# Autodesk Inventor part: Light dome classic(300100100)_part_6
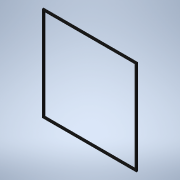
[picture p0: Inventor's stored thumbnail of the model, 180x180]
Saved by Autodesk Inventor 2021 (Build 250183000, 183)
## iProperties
Created: 2026-04
Part Number: Light dome classic(300100100)_part_6
Material: Generic
Catalog Web Link: www.3dfindit.com
Description: Light dome classic_part_6-
Vendor: KINGSPAN
Document SubType Name: Modeling
Designer: psAdmin
Manufacturer: KINGSPAN
Mass: 791.394 g
Surface Area: 2091.11 cm^2
Volume: 791.394 cm^3
Density: 1 g/cm^3
Appearance: PSOLRGB-128-128-128
Category: PARTsolutions
Company: KINGSPAN
Title: Light dome classic(300100100)_part_6
Author: Cadenas PARTsolutions
PSOL_IDENT_0: {$CADENAS_DATA/23d-libs/kingspan_kla/light_dome_classic/parts/part_6.prj},244 {VTYP=3D},{NB=Light do
PSOL_IDENT_1: me classic(300100100)_part_6},{LINA=Light dome classic(300100100)_part_6},{NN=Light dome classic_par
PSOL_IDENT_2: t_6},{DATE=20.03.2025 09:30:52},{GEOMDATE=04.11.2022 12:03:00},{VERSION=},{LINEID=10},{WBVAR=LODLEVE
PSOL_IDENT_3: L,L,W},{WBNUMERIC=W}  {NB=Light dome classic(300100100)_part_6},{LINA=Light dome classic(300100100)_
PSOL_IDENT_4: part_6},{KT=DUMMY},{IDNR=},{PN=Light dome classic},{LODLEVEL=300},{L=100},{W=100},{WX=100,150,200,25
PSOL_IDENT_5: 0,300},{LX=1000},{XWX=1000}
NB: Light dome classic(300100100)_part_6
NN: Light dome classic_part_6
NBSYN: $PN.($LODLEVEL.$L.$W.)_part_6
LINA: Light dome classic(300100100)_part_6
CATALOG: Light + Air
PN: Light dome classic
LODLEVEL: 300
L: 100
W: 100
SUPPLIER: KINGSPAN
ARTICLENO: Light dome classic(300100100)_part_6
BOMINFO: Light dome classic(300100100)_part_6
CREATOR: CADENAS GmbH
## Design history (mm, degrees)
sketch "Sketch_1"
  geometry: L1 (-423.235, 1.946)-(-423.235, 17.946); L2 (-423.235, 17.946)-(-437.6, 17.946); L3 (-437.6, 17.946)-(-437.6, 1.946); L4 (-437.6, 1.946)-(-423.235, 1.946)
  constraints: 8 end point
extrude "Extrusion1" join sketch "Sketch_1" stored distance "d0" = 2000; taper "d1" = 0 deg
sketch "Sketch_2"
  geometry: L1 (423.235, 17.946)-(423.235, 1.946); L2 (423.235, 1.946)-(437.6, 1.946); L3 (437.6, 1.946)-(437.6, 17.946); L4 (437.6, 17.946)-(423.235, 17.946)
  constraints: 8 end point
extrude "Extrusion2" join sketch "Sketch_2" stored distance "d2" = 2000; taper "d3" = 0 deg
sketch "Sketch_3"
  geometry: L1 (437.6, 1.946)-(437.6, 17.946); L2 (437.6, 17.946)-(423.235, 17.946); L3 (423.235, 17.946)-(423.235, 1.946); L4 (423.235, 1.946)-(437.6, 1.946)
  constraints: 8 end point
extrude "Extrusion3" join sketch "Sketch_3" stored distance "d4" = 2000; taper "d5" = 0 deg
sketch "Sketch_4"
  geometry: L1 (-423.235, 17.946)-(-437.6, 17.946); L2 (-437.6, 17.946)-(-437.6, 1.946); L3 (-437.6, 1.946)-(-423.235, 1.946); L4 (-423.235, 1.946)-(-423.235, 17.946)
  constraints: 8 end point
extrude "Extrusion4" join sketch "Sketch_4" stored distance "d6" = 2000; taper "d7" = 0 deg
sketch "Sketch_5"
  geometry: L1 (-429.25, 37.946)-(-1000, 37.946); L2 (-1000, 37.946)-(-1000, -12.054); L3 (-1000, -12.054)-(-437.6, -12.054); L4 (-437.6, -12.054)-(-437.6, 17.946); L5 (-437.6, 17.946)-(-429.25, 17.946); L6 (-429.25, 17.946)-(-429.25, 37.946)
  constraints: 12 end point
extrude "Extrusion5" cut sketch "Sketch_5" stored distance "d8" = 2000; taper "d9" = 0 deg
sketch "Sketch_6"
  geometry: L1 (1000, -12.054)-(1000, 37.946); L2 (1000, 37.946)-(429.25, 37.946); L3 (429.25, 37.946)-(429.25, 17.946); L4 (429.25, 17.946)-(437.6, 17.946); L5 (437.6, 17.946)-(437.6, -12.054); L6 (437.6, -12.054)-(1000, -12.054)
  constraints: 12 end point
extrude "Extrusion6" cut sketch "Sketch_6" stored distance "d10" = 2000; taper "d11" = 0 deg
sketch "Sketch_7"
  geometry: L1 (1000, 37.946)-(429.25, 37.946); L2 (429.25, 37.946)-(429.25, 17.946); L3 (429.25, 17.946)-(437.6, 17.946); L4 (437.6, 17.946)-(437.6, -12.054); L5 (437.6, -12.054)-(1000, -12.054); L6 (1000, -12.054)-(1000, 37.946)
  constraints: 12 end point
extrude "Extrusion7" cut sketch "Sketch_7" stored distance "d12" = 2000; taper "d13" = 0 deg
sketch "Sketch_8"
  geometry: L1 (-1000, 37.946)-(-1000, -12.054); L2 (-1000, -12.054)-(-437.6, -12.054); L3 (-437.6, -12.054)-(-437.6, 17.946); L4 (-437.6, 17.946)-(-429.25, 17.946); L5 (-429.25, 17.946)-(-429.25, 37.946); L6 (-429.25, 37.946)-(-1000, 37.946)
  constraints: 12 end point
extrude "Extrusion8" cut sketch "Sketch_8" stored distance "d14" = 2000; taper "d15" = 0 deg
node "IP_6_XY"
node "IP_6_YZ"
node "IP_6_ZX"
node "IP_6_X"
node "IP_6_Y"
node "IP_6_Z"
node "IP_6_Center"
body "Solid1"
other parameters: "d16" = 0
